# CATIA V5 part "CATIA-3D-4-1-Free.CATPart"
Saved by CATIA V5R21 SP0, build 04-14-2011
Part number: CATIA-3D-4-1-Free
Bounding box of the stored display mesh (mm): x -141.992 to 33.968, y 0 to 52, z -34 to 101
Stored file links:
  C:\Users\Rasoul Mohammadi\Desktop\CATIA-Free\3D\CATIA-3D-4-1-Free.CATPart
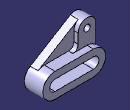
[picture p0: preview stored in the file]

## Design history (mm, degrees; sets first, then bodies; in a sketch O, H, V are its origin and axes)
Body1 (main body)
  Sketch1 on zx-plane, origin (0, 0, 0), H (-1, 0, 0), V (0, 0, 1)
    construction line L1 (0, 0) -> (108, 0)
    line L2 (0, 15) -> (108, 15)
    line L3 (108, -15) -> (0, -15)
    arc A1 centre (108, 0) radius 15 from (108, 15) to (108, -15) cw
    arc A2 centre (0, 0) radius 15 from (0, -15) to (0, 15) cw
    construction line L4 (0, 0) -> (108, 0)
    line L5 (0, 34) -> (108, 34)
    line L6 (108, -34) -> (0, -34)
    arc A3 centre (108, 0) radius 34 from (108, 34) to (108, -34) cw
    arc A4 centre (0, 0) radius 34 from (0, -34) to (0, 34) cw
    distance L1 L2 = 15
    distance L4 L5 = 34
    length L4 = 108
    horizontal: L1 H, L4 H
    tangency: A1 L2, A2 L2, A1 L3, A2 L3, A3 L5, A4 L5, A3 L6, A4 L6
  Pad1: profile Sketch1, direction (0, 1, 0), length 52
  Sketch2 on zx-plane, origin (0, 0, 0), H (-1, 0, 0), V (0, 0, 1)
    arc A1 centre (108, 76) radius 25 from (133, 76) to (83, 76) ccw
    axis line L1 (108, 0) -> (108, 76)
    point P2 (108, 0)
    reference projected arc E1 centre (108, 0) radius 15 from (108, -15) to (108, 15) ccw from edge [end face of Pad1 | face of Pad1 from Sketch1.A1]
    projected arc E2 centre (108, 0) radius 34 from (108, -34) to (108, 34) ccw from edge [face of Pad1 from Sketch1.A3 | end face of Pad1]
    projected arc E3 centre (108, 0) radius 34 from (133, 23.0434) to (108, 34) ccw from edge [face of Pad1 from Sketch1.A3 | end face of Pad1]
    point P4 (108, 34)
    projected line E4 (108, 34) -> (0, 34) from edge [face of Pad1 from Sketch1.L5 | end face of Pad1]
    projected line E5 (108, 34) -> (83, 34) from edge [face of Pad1 from Sketch1.L5 | end face of Pad1]
    point P5 (108, 34)
    line L2 (133, 76) -> (133, 23.0434)
    line L3 (83, 76) -> (83, 34)
    circle A2 centre (108, 76) radius 9
    point P11 (108, 85)
    radius A1 = 25
    length L1 = 76
    radius A2 = 9
    coincidence: P2 H, A2 P11, P11 L1, P4 P5
    vertical: L1 V, L2 V, L3 V
    concentricity: P2 E1
    tangency: L2 A1, L3 A1
  Pad2: profile Sketch2, direction (0, 1, 0), length 34
  Fillet1: radius 15, on edge [face of Pad1 from Sketch1.L5 | face of Pad2 from Sketch2.L3]
  Sketch3 on zx-plane, origin (0, 0, 0), H (-1, 0, 0), V (0, 0, 1)
    projected line E1 (108, 34) -> (0, 34) from edge [face of Pad1 from Sketch1.L5 | end face of Pad1]
    projected line E2 (68, 34) -> (0, 34) from edge [face of Pad1 from Sketch1.L5 | end face of Pad1]
    point P2 (0, 34)
    projected arc E3 centre (0, 0) radius 34 from (0, 34) to (0, -34) ccw from edge [face of Pad1 from Sketch1.A4 | end face of Pad1]
    projected arc E4 centre (0, 0) radius 34 from (0, 34) to (-17.6263, 29.0743) ccw from edge [face of Pad1 from Sketch1.A4 | end face of Pad1]
    point P3 (0, 34)
    projected arc E5 centre (68, 49) radius 15 from (68, 34) to (83, 49) ccw from edge [face of Fillet1 | end face of Pad2]
    projected arc E6 centre (68, 49) radius 15 from (68, 34) to (83, 49) ccw from edge [face of Fillet1 | end face of Pad2]
    point P6 (83, 49)
    projected line E7 (83, 76) -> (83, 49) from edge [face of Pad2 from Sketch2.L3 | end face of Pad2]
    point P7 (83, 76)
    point P8 (83, 49)
    projected arc E8 centre (108, 76) radius 25 from (133, 76) to (83, 76) ccw from edge [face of Pad2 from Sketch2.A1 | end face of Pad2]
    projected arc E9 centre (108, 76) radius 25 from (95.0395, 97.3781) to (83, 76) ccw from edge [face of Pad2 from Sketch2.A1 | end face of Pad2]
    point P10 (83, 76)
    line L1 (95.0395, 97.3781) -> (-17.6263, 29.0743)
    tangency: L1 E8, L1 E3
    coincidence: P2 P3, P6 P8, P7 P10
  Pad3: profile Sketch3, direction (0, 1, 0), length 22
